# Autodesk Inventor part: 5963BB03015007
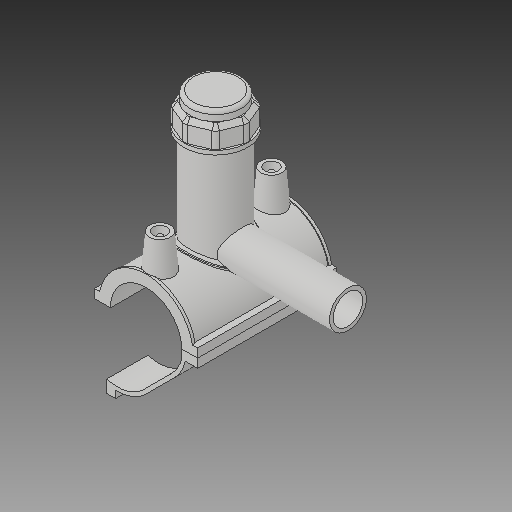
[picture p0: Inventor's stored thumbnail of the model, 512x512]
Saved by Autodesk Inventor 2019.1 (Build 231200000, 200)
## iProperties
Created: 2017-07
Part Number: 5963BB03015007
Material: Generic
Description: PLASSON TAPPING SADDLE 1 1/2''IPS x 1 3/4''IPS
Document SubType Name: Modeling
Designer: KIM
Mass: 1712.7 g
Surface Area: 2671.49 cm^2
Volume: 1712.7 cm^3
Density: 1 g/cm^3
Appearance: Default
Author: KIM
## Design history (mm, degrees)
derived "5963B.ipt"
feature "Solid1::5963B.ipt"
feature "Solid2::5963B.ipt"
feature "Solid4::5963B.ipt"
feature "Solid5::5963B.ipt"
tag "TaggingFeature1"
body "Solid1"
body "Solid2"
other parameters: "d0" = 51.1, "d2" = 74.168, "d3" = 12.775, "d4" = 100.076, "d5" = 0, "d6" = 0.1, "d8" = 0, "d19" = 6, "d20" = 6, "d21" = 60.0456, "d23" = 0, "d24" = 30.0228, "d26" = 0, "d29" = 3, "d30" = 17.03333, "d31" = 6, "d32" = 0, "d33" = 0, "d34" = 0.6, "d40" = 34.5436, "d41" = 45.99, "d43" = 0, "d45" = 0, "d47" = 93.2606, "d70" = 15, "d72" = 0, "d73" = 6, "d75" = 5, "d76" = 0, "d77" = 2.555, "d78" = 55.55, "d79" = 15, "d80" = 40.0304, "d82" = 5 deg, "d84" = 4, "d85" = 14, "d86" = 0, "d87" = 3, "d88" = 0, "d89" = 1, "d90" = 1, "d91" = 80.0608, "d92" = 0, "d93" = 0.5, "d94" = 26.89474, "d96" = 67.7586, "d97" = 2.00152, "d98" = 0, "d102" = 0.511, "d120" = 140 deg, "d121" = 24.228, "d122" = 20 deg, "d123" = 132.86, "d124" = 39.858, "d126" = 0, "d143" = 52.633, "d145" = 11.79231, "d149" = 0.7665, "d150" = 12.97154, "d153" = 100.076, "d154" = 0, "d156" = 33.215, "d157" = 160 deg, "d159" = 3.066, "d161" = 0.7665, "d162" = 60.0456, "d163" = 0, "d164" = 25.55, "d167" = 5.11, "d168" = 32.40488, "d170" = 3.2805, "d172" = 0, "d173" = 1, "d175" = 25.55, "d176" = 20 deg, "d177" = 3.577, "d178" = 15.33, "d180" = 0, "d183" = 6.132, "d184" = 2.8616, "d185" = 32.5247, "d186" = 32.5247, "d187" = 33.215, "d188" = 4.599, "d189" = 3.577, "d190" = 0, "d191" = 49.8225, "d193" = 6.1236, "d194" = 3.50266, "d195" = 90 deg, "d197" = 0, "d199" = 0, "d200" = 7.665, "d202" = 0, "d203" = 98.044, "d204" = 43.6905, "d205" = 32.193, "d206" = 39.0915, "d207" = 73.533, "d208" = 76.47432, "d209" = 91.18092, "d210" = 39.5514, "d211" = 45.99, "d212" = 36.792, "d213" = -3.969, "d216" = 0, "d217" = 5.11, "d218" = 2.555, "d219" = 0.511, "d222" = 51.1, "d224" = 0, "d230" = 3.066, "d233" = 6, "d236" = 37.084, "d237" = 30.0228, "d238" = 6.02433, "d240" = 30.0228, "d241" = 30.0228, "d242" = 30.0228, "d243" = 6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
